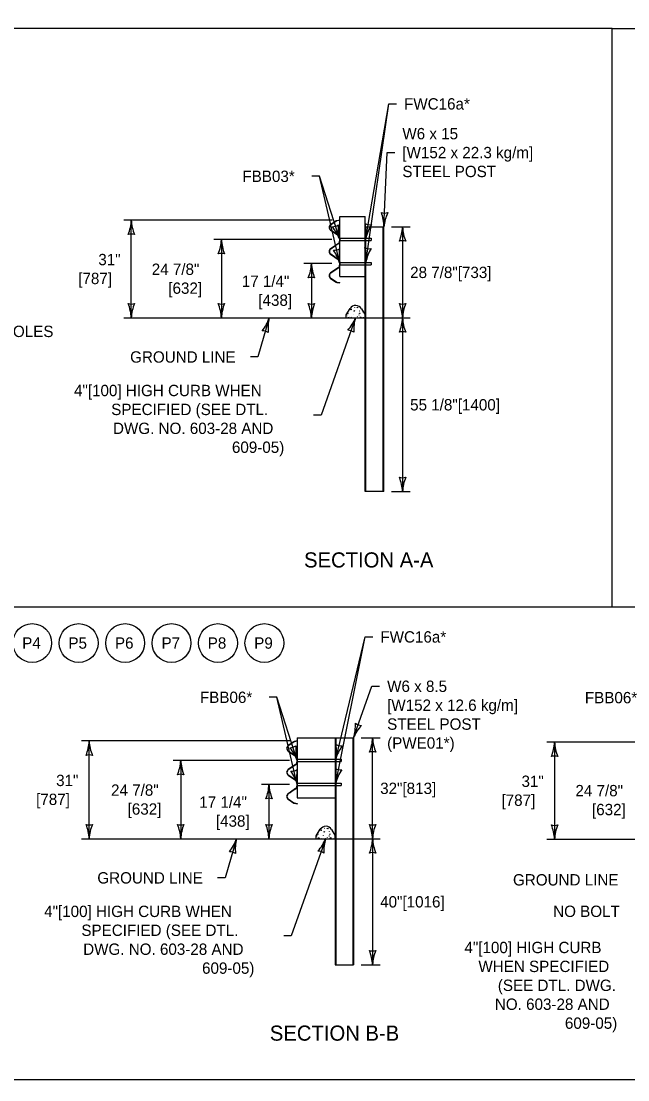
# Model space of a CAD drawing. Extents: x 49991 to 50160, y 49948 to 50051.
# Drawn here: x 50003.35 to 50006.56, y 49987.8 to 49993.4 of the extents above; entities that cross this region are included whole.
import ezdxf

# ---------------------------------------------------------------- set-up
doc = ezdxf.new("R2010")
doc.units = 0
for name, color, linetype in [('Level 1', 7, 'Continuous'), ('Level 2', 7, 'Continuous'), ('Level 3', 7, 'Continuous'), ('Level 4', 7, 'Continuous')]:
    doc.layers.add(name, color=color, linetype=linetype)

msp = doc.modelspace()

# ---------------------------------------------------------------- linework, layer by layer
at = {"layer": 'Level 1'}
for p, q in [((50005.0342, 49992.0461), (50005.0342, 49992.3628)), ((50005.0342, 49992.3628), (50005.1675, 49992.3628)), ((50005.1675, 49992.0461), (50005.1675, 49992.3628)), ((50004.9843, 49992.2945), (50004.9831, 49992.2932)), ((50005.0155, 49992.3402), (50004.9857, 49992.3201)), ((50005.0164, 49992.3388), (50004.9866, 49992.3186)), ((50005.0342, 49992.3443), (50005.0183, 49992.3414)), ((50005.0345, 49992.3426), (50005.0186, 49992.3397)), ((50005.0342, 49992.3443), (50005.032, 49992.3421)), ((50005.0345, 49992.3426), (50005.0342, 49992.3443)), ((50005.1675, 49990.9086), (50005.1675, 49992.3086)), ((50005.1675, 49992.3086), (50005.2675, 49992.3086)), ((50005.1718, 49990.9086), (50005.1718, 49992.3086)), ((50005.2632, 49990.9086), (50005.2632, 49992.3086)), ((50005.2675, 49990.9086), (50005.2675, 49992.3086)), ((50004.9857, 49992.2911), (50005.0255, 49992.2642)), ((50004.9866, 49992.2925), (50005.0265, 49992.2656)), ((50005.0193, 49992.2705), (50005.018, 49992.2692)), ((50005.0324, 49992.2511), (50005.0324, 49992.2328)), ((50005.0342, 49992.2511), (50005.0342, 49992.2328)), ((50005.1718, 49992.2482), (50005.2008, 49992.2482)), ((50005.2008, 49992.2482), (50005.2009, 49992.2357)), ((50005.0255, 49992.2197), (50004.9857, 49992.1928)), ((50005.0265, 49992.2183), (50004.9866, 49992.1913)), ((50005.1718, 49992.2357), (50005.2009, 49992.2357)), ((50004.9857, 49992.1638), (50005.0255, 49992.1369)), ((50004.9866, 49992.1652), (50005.0265, 49992.1383)), ((50005.0136, 49992.147), (50005.0124, 49992.1457)), ((50005.0255, 49992.0924), (50004.9857, 49992.0655)), ((50005.0265, 49992.091), (50004.9866, 49992.064)), ((50005.0023, 49992.0768), (50004.9958, 49992.0702)), ((50005.0324, 49992.1238), (50005.0324, 49992.1055)), ((50005.0342, 49992.1086), (50005.0324, 49992.1068)), ((50005.0342, 49992.1238), (50005.0342, 49992.1055)), ((50005.1718, 49992.1211), (50005.2008, 49992.1211)), ((50005.1718, 49992.1086), (50005.2009, 49992.1086)), ((50005.2008, 49992.1211), (50005.2009, 49992.1086)), ((50004.9801, 49992.0545), (50004.978, 49992.0524)), ((50004.9857, 49992.0365), (50005.0155, 49992.0164)), ((50004.9866, 49992.0379), (50005.0164, 49992.0178)), ((50005.0183, 49992.0152), (50005.0342, 49992.0123)), ((50005.0186, 49992.0169), (50005.0345, 49992.014)), ((50005.0342, 49992.0461), (50005.1675, 49992.0461)), ((50005.0342, 49992.0123), (50005.0345, 49992.014)), ((50005.0675, 49991.8434), (50005.0889, 49991.8773)), ((50005.1118, 49991.8838), (50005.1123, 49991.883)), ((50005.1374, 49991.8639), (50005.1379, 49991.8651)), ((50005.1376, 49991.8499), (50005.1388, 49991.8524)), ((50005.1487, 49991.8756), (50005.1675, 49991.8434)), ((50005.1577, 49991.8584), (50005.1581, 49991.8595)), ((50005.0675, 49991.8294), (50005.0675, 49991.8434)), ((50005.0675, 49991.8294), (50005.1675, 49991.8274)), ((50005.0707, 49991.843), (50005.0712, 49991.8422)), ((50005.0712, 49991.8427), (50005.0717, 49991.8419)), ((50005.0951, 49991.83), (50005.0956, 49991.8312)), ((50005.1059, 49991.843), (50005.1064, 49991.8442)), ((50005.1175, 49991.8284), (50005.1175, 49991.8284)), ((50005.1175, 49991.8284), (50005.1175, 49991.8284)), ((50005.1267, 49991.8331), (50005.1272, 49991.8343)), ((50005.1346, 49991.843), (50005.1351, 49991.8422)), ((50005.1351, 49991.8427), (50005.1356, 49991.8419)), ((50005.159, 49991.83), (50005.1595, 49991.8312)), ((50005.1675, 49991.8274), (50005.1675, 49991.8434)), ((50005.2675, 49990.9086), (50005.1675, 49990.9086)), ((49999.3835, 49990.2991), (50008.2653, 49990.2991)), ((50004.7911, 49989.5862), (50004.7613, 49989.5661)), ((50004.7921, 49989.5848), (50004.7623, 49989.5647)), ((50004.8099, 49989.5903), (50004.794, 49989.5874)), ((50004.8102, 49989.5886), (50004.7943, 49989.5857)), ((50004.8099, 49989.5903), (50004.8077, 49989.5881)), ((50004.8099, 49989.6067), (50004.8099, 49989.29)), ((50004.8099, 49989.6067), (50005.0099, 49989.6067)), ((50004.8102, 49989.5886), (50004.8099, 49989.5903)), ((50005.0099, 49989.6067), (50005.0099, 49989.29)), ((50005.0099, 49989.6067), (50005.0099, 49988.4067)), ((50005.0099, 49989.6067), (50005.107, 49989.6067)), ((50005.0131, 49989.6067), (50005.0131, 49988.4067)), ((50005.1038, 49989.6067), (50005.1038, 49988.4067)), ((50005.107, 49989.6067), (50005.107, 49988.4067)), ((50004.76, 49989.5405), (50004.7588, 49989.5392)), ((50004.7613, 49989.5371), (50004.8012, 49989.5102)), ((50004.7623, 49989.5386), (50004.8022, 49989.5117)), ((50004.795, 49989.5165), (50004.7937, 49989.5152)), ((50004.8081, 49989.4972), (50004.8081, 49989.4788)), ((50004.8099, 49989.4972), (50004.8099, 49989.4788)), ((50004.8012, 49989.4657), (50004.7613, 49989.4388)), ((50004.8022, 49989.4643), (50004.7623, 49989.4374)), ((50005.0131, 49989.4942), (50005.0421, 49989.4942)), ((50005.0131, 49989.4817), (50005.0421, 49989.4817)), ((50005.0421, 49989.4942), (50005.0421, 49989.4817)), ((50004.7613, 49989.4098), (50004.8012, 49989.3829)), ((50004.7623, 49989.4113), (50004.8022, 49989.3844)), ((50004.7893, 49989.393), (50004.7881, 49989.3918)), ((50004.8012, 49989.3384), (50004.7613, 49989.3115)), ((50004.8022, 49989.337), (50004.7623, 49989.3101)), ((50004.8081, 49989.3699), (50004.8081, 49989.3515)), ((50004.8099, 49989.3546), (50004.8081, 49989.3529)), ((50004.8099, 49989.3699), (50004.8099, 49989.3515)), ((50005.0131, 49989.3671), (50005.0421, 49989.3671)), ((50005.0131, 49989.3546), (50005.0421, 49989.3546)), ((50005.0421, 49989.3671), (50005.0421, 49989.3546)), ((50004.7558, 49989.3006), (50004.7537, 49989.2985)), ((50004.7613, 49989.2825), (50004.7911, 49989.2624)), ((50004.7623, 49989.284), (50004.7921, 49989.2638)), ((50004.778, 49989.3228), (50004.7715, 49989.3163)), ((50004.8099, 49989.29), (50005.0099, 49989.29)), ((50004.794, 49989.2612), (50004.8099, 49989.2583)), ((50004.7943, 49989.263), (50004.8102, 49989.26)), ((50004.8099, 49989.2583), (50004.8102, 49989.26)), ((50004.9099, 49989.0894), (50004.9312, 49989.1233)), ((50004.9541, 49989.1298), (50004.9546, 49989.129)), ((50004.9797, 49989.1099), (50004.9802, 49989.1111)), ((50004.991, 49989.1217), (50005.0099, 49989.0894)), ((50005, 49989.1045), (50005.0005, 49989.1055)), ((50004.9099, 49989.0754), (50004.9099, 49989.0894)), ((50004.9099, 49989.0754), (50005.0099, 49989.0734)), ((50004.913, 49989.089), (50004.9135, 49989.0882)), ((50004.9135, 49989.0887), (50004.9141, 49989.0879)), ((50004.9374, 49989.076), (50004.938, 49989.0772)), ((50004.9482, 49989.089), (50004.9488, 49989.0902)), ((50004.9599, 49989.0744), (50004.9599, 49989.0744)), ((50004.9599, 49989.0744), (50004.9599, 49989.0744)), ((50004.969, 49989.0791), (50004.9696, 49989.0803)), ((50004.9769, 49989.089), (50004.9774, 49989.0882)), ((50004.9774, 49989.0887), (50004.978, 49989.0879)), ((50004.98, 49989.0959), (50004.9812, 49989.0984)), ((50005.0013, 49989.076), (50005.0019, 49989.0772)), ((50005.0099, 49989.0734), (50005.0099, 49989.0894)), ((50005.0099, 49988.4067), (50005.107, 49988.4067))]:
    msp.add_line(p, q, dxfattribs=at)
msp.add_lwpolyline([(49999.3835, 49998.9992), (50016.7501, 49998.9992), (50016.7501, 49987.7988), (49999.3835, 49987.7988)], close=True, dxfattribs=at)
for points in [[(50006.474, 49990.2991), (50006.474, 49993.358), (49999.3835, 49993.358)], [(50006.474, 49993.358), (50011.2031, 49993.358), (50011.2031, 49987.7988)], [(50005.0737, 49991.8499), (50005.0753, 49991.8532), (50005.078, 49991.8512), (50005.0737, 49991.8499)], [(50005.0911, 49991.8708), (50005.0927, 49991.8741), (50005.0954, 49991.8721), (50005.0911, 49991.8708)], [(50005.1091, 49991.8626), (50005.1097, 49991.8665), (50005.1134, 49991.8626)], [(50005.1258, 49991.8803), (50005.1274, 49991.8837), (50005.13, 49991.8817), (50005.1258, 49991.8803)], [(50005.1403, 49991.8524), (50005.1419, 49991.8512), (50005.1376, 49991.8499)], [(50005.0785, 49991.8291), (50005.0807, 49991.8332), (50005.0825, 49991.8291)], [(50005.1417, 49991.8279), (50005.1446, 49991.8332), (50005.147, 49991.8278)], [(50004.9334, 49989.1168), (50004.935, 49989.1201), (50004.9377, 49989.1181), (50004.9334, 49989.1168)], [(50004.9515, 49989.1087), (50004.952, 49989.1125), (50004.9557, 49989.1087)], [(50004.9681, 49989.1263), (50004.9697, 49989.1297), (50004.9724, 49989.1277), (50004.9681, 49989.1263)], [(50004.9161, 49989.0959), (50004.9177, 49989.0993), (50004.9203, 49989.0973), (50004.9161, 49989.0959)], [(50004.9209, 49989.0752), (50004.923, 49989.0792), (50004.9249, 49989.0751)], [(50004.9827, 49989.0984), (50004.9842, 49989.0973), (50004.98, 49989.0959)], [(50004.9841, 49989.0739), (50004.9869, 49989.0792), (50004.9894, 49989.0738)]]:
    msp.add_lwpolyline(points, dxfattribs=at)
for centre, radius, start, end in [((50004.9955, 49992.3056), 0.0175, 124.048, 235.952), ((50004.9955, 49992.3056), 0.0157, 124.048, 235.952), ((50005.0196, 49992.3341), 0.00744, 100.4285, 124.048), ((50005.0196, 49992.3341), 0.00569, 100.4285, 124.048), ((50005.0167, 49992.2511), 0.0157, 0, 55.952), ((50005.0167, 49992.2511), 0.0175, 0, 55.952), ((50004.9955, 49992.1783), 0.0175, 124.048, 235.952), ((50004.9955, 49992.1783), 0.0157, 124.048, 235.952), ((50005.0167, 49992.2328), 0.0157, 304.048, 0), ((50005.0167, 49992.2328), 0.0175, 304.048, 0), ((50005.0167, 49992.1238), 0.0157, 0, 55.952), ((50005.0167, 49992.1238), 0.0175, 0, 55.952), ((50005.0167, 49992.1055), 0.0157, 304.048, 0), ((50005.0167, 49992.1055), 0.0175, 304.048, 0), ((50004.9955, 49992.051), 0.0175, 124.048, 235.952), ((50004.9955, 49992.051), 0.0157, 124.048, 235.952), ((50005.0196, 49992.0225), 0.00744, 235.952, 259.5715), ((50005.0196, 49992.0225), 0.00569, 235.952, 259.5715), ((50005.1183, 49991.8579), 0.0352, 30.1855, 146.6195), ((50004.7711, 49989.5516), 0.0175, 124.048, 235.952), ((50004.7711, 49989.5516), 0.0157, 124.048, 235.952), ((50004.7953, 49989.5801), 0.00744, 100.4285, 124.048), ((50004.7953, 49989.5801), 0.00569, 100.4285, 124.048), ((50004.7924, 49989.4972), 0.0157, 0, 55.952), ((50004.7924, 49989.4972), 0.0175, 0, 55.952), ((50004.7924, 49989.4788), 0.0157, 304.048, 0), ((50004.7924, 49989.4788), 0.0175, 304.048, 0), ((50004.7711, 49989.4243), 0.0175, 124.048, 235.952), ((50004.7711, 49989.4243), 0.0157, 124.048, 235.952), ((50004.7924, 49989.3699), 0.0175, 0, 55.952), ((50004.7924, 49989.3699), 0.0157, 0, 55.952), ((50004.7924, 49989.3515), 0.0157, 304.048, 0), ((50004.7924, 49989.3515), 0.0175, 304.048, 0), ((50004.7711, 49989.297), 0.0175, 124.048, 235.952), ((50004.7711, 49989.297), 0.0157, 124.048, 235.952), ((50004.7953, 49989.2685), 0.00744, 235.952, 259.5715), ((50004.7953, 49989.2685), 0.00569, 235.952, 259.5715), ((50004.9606, 49989.104), 0.0352, 30.1855, 146.6195)]:
    msp.add_arc(centre, radius, start, end, dxfattribs=at)
at = {"layer": 'Level 2'}
for centre in [(50003.4096, 49990.1082), (50003.6549, 49990.1082), (50003.9002, 49990.1082), (50004.1455, 49990.1082), (50004.3908, 49990.1082), (50004.6361, 49990.1082)]:
    msp.add_circle(centre, 0.1026, dxfattribs=at)
at = {"layer": 'Level 3'}
for p, q in [((50005.1718, 49992.2482), (50005.2938, 49992.959)), ((50005.1718, 49992.1211), (50005.2938, 49992.959)), ((50005.2938, 49992.959), (50005.3338, 49992.959)), ((50005.2675, 49992.3086), (50005.2849, 49992.7016)), ((50005.2849, 49992.7016), (50005.3249, 49992.7016)), ((50004.9263, 49992.5759), (50004.8863, 49992.5759)), ((50005.0342, 49992.2419), (50004.9263, 49992.5759)), ((50005.0342, 49992.115), (50004.9263, 49992.5759)), ((50004.9942, 49992.3443), (50003.893, 49992.3443)), ((50003.933, 49991.8273), (50003.933, 49992.3443)), ((50005.3075, 49992.3086), (50005.4059, 49992.3086)), ((50005.3659, 49992.3086), (50005.3659, 49991.8274)), ((50004.9924, 49992.2419), (50004.3689, 49992.2419)), ((50004.4089, 49992.2419), (50004.4089, 49991.8273)), ((50004.9924, 49992.1146), (50004.8444, 49992.1146)), ((50004.8844, 49992.1146), (50004.8844, 49991.8273)), ((50003.893, 49991.8274), (50005.4059, 49991.8274)), ((50004.6615, 49991.8274), (50004.6018, 49991.6207)), ((50005.1175, 49991.8284), (50004.9357, 49991.3135)), ((50005.3659, 49991.8274), (50005.3659, 49990.9086)), ((50004.6018, 49991.6207), (50004.5618, 49991.6207)), ((50004.9357, 49991.3135), (50004.8957, 49991.3135)), ((50005.3075, 49990.9086), (50005.4059, 49990.9086)), ((50005.0131, 49989.4942), (50005.1688, 49990.1406)), ((50005.0131, 49989.3671), (50005.1688, 49990.1406)), ((50005.1688, 49990.1406), (50005.2088, 49990.1406)), ((50005.107, 49989.6067), (50005.2044, 49989.8797)), ((50005.2044, 49989.8797), (50005.2444, 49989.8797)), ((50004.702, 49989.8213), (50004.662, 49989.8213)), ((50004.8099, 49989.4874), (50004.702, 49989.8213)), ((50004.8099, 49989.3611), (50004.702, 49989.8213)), ((50004.7699, 49989.5903), (50003.6705, 49989.5903)), ((50003.7105, 49989.0734), (50003.7105, 49989.5903)), ((50005.147, 49989.6067), (50005.2476, 49989.6067)), ((50005.2076, 49989.0734), (50005.2076, 49989.6067)), ((50006.7634, 49989.5842), (50006.1288, 49989.5842)), ((50006.1688, 49989.5842), (50006.1688, 49989.0706)), ((50004.7681, 49989.488), (50004.154, 49989.488)), ((50004.194, 49989.488), (50004.194, 49989.0734)), ((50004.7681, 49989.3607), (50004.6201, 49989.3607)), ((50004.6601, 49989.3607), (50004.6601, 49989.0734)), ((50003.6705, 49989.0734), (50005.2476, 49989.0734)), ((50004.4884, 49989.0734), (50004.4287, 49988.8667)), ((50004.9599, 49989.0744), (50004.778, 49988.5595)), ((50005.2076, 49989.0734), (50005.2076, 49988.4067)), ((50006.1288, 49989.0706), (50007.2412, 49989.0706)), ((50004.4287, 49988.8667), (50004.3887, 49988.8667)), ((50004.778, 49988.5595), (50004.738, 49988.5595)), ((50005.147, 49988.4067), (50005.2476, 49988.4067))]:
    msp.add_line(p, q, dxfattribs=at)
for centre, radius, start, end in [((50005.2732, 49992.4367), 0.0548, 249.601, 285.3234), ((50005.0345, 49992.3074), 0.233, 0.2895, 19.5394), ((50005.489, 49992.2896), 0.2223, 154.9182, 175.1017), ((50003.7109, 49992.3535), 0.2223, 337.456, 357.6395), ((50004.1657, 49992.3558), 0.233, 182.8273, 202.0772), ((50004.9948, 49992.3639), 0.0548, 270.0345, 305.7569), ((50004.8163, 49992.1595), 0.233, 20.723, 39.9729), ((50005.2484, 49992.3015), 0.2223, 175.3517, 195.5352), ((50005.1935, 49992.3746), 0.0548, 242.4025, 278.1249), ((50004.9405, 49992.2762), 0.233, 353.091, 12.3408), ((50005.3892, 49992.2016), 0.2223, 147.7197, 167.9032), ((50005.1437, 49992.3178), 0.2223, 337.456, 357.6395), ((50005.5986, 49992.3201), 0.233, 182.8273, 202.0772), ((50003.933, 49992.2161), 0.0548, 72.1388, 107.8612), ((50004.1868, 49992.2511), 0.2223, 337.456, 357.6395), ((50004.6416, 49992.2534), 0.233, 182.8273, 202.0772), ((50005.005, 49992.2398), 0.0548, 265.3085, 301.0309), ((50004.8102, 49992.0508), 0.233, 15.997, 35.2468), ((50005.2526, 49992.1567), 0.2223, 170.6257, 190.8092), ((50005.1903, 49992.248), 0.0548, 243.857, 279.5794), ((50004.9399, 49992.1433), 0.233, 354.5455, 13.7954), ((50005.3903, 49992.08), 0.2223, 149.1742, 169.3577), ((50005.3659, 49992.1804), 0.0548, 72.1388, 107.8612), ((50004.4089, 49992.1137), 0.0548, 72.1388, 107.8612), ((50004.6623, 49992.1238), 0.2223, 337.456, 357.6395), ((50005.1171, 49992.1261), 0.233, 182.8273, 202.0772), ((50004.8844, 49991.9864), 0.0548, 72.1388, 107.8612), ((50003.933, 49991.9556), 0.0548, 252.1388, 287.8612), ((50003.7003, 49991.8159), 0.233, 2.8273, 22.0772), ((50004.1552, 49991.8182), 0.2223, 157.456, 177.6395), ((50004.4089, 49991.9556), 0.0548, 252.1388, 287.8612), ((50004.1762, 49991.8159), 0.233, 2.8273, 22.0772), ((50004.631, 49991.8182), 0.2223, 157.456, 177.6395), ((50004.8844, 49991.9556), 0.0548, 252.1388, 287.8612), ((50004.6517, 49991.8159), 0.233, 2.8273, 22.0772), ((50005.1066, 49991.8182), 0.2223, 157.456, 177.6395), ((50005.3659, 49991.9556), 0.0548, 252.1388, 287.8612), ((50005.1332, 49991.8159), 0.233, 2.8273, 22.0772), ((50005.588, 49991.8182), 0.2223, 157.456, 177.6395), ((50004.4507, 49991.8978), 0.2223, 321.3407, 341.5242), ((50004.8883, 49991.7738), 0.233, 166.712, 185.9619), ((50004.9111, 49991.911), 0.2223, 318.0037, 338.1872), ((50005.3408, 49991.7617), 0.233, 163.375, 182.6248), ((50005.1437, 49991.8365), 0.2223, 337.456, 357.6395), ((50005.5986, 49991.8388), 0.233, 182.8273, 202.0772), ((50004.626, 49991.7042), 0.0548, 56.0235, 91.7459), ((50005.0748, 49991.7075), 0.0548, 52.6865, 88.4089), ((50005.3659, 49991.6991), 0.0548, 72.1388, 107.8612), ((50005.3659, 49991.0368), 0.0548, 252.1388, 287.8612), ((50005.1332, 49990.8971), 0.233, 2.8273, 22.0772), ((50005.588, 49990.8994), 0.2223, 157.456, 177.6395), ((50004.884, 49989.6741), 0.233, 343.1881, 2.438), ((50005.3131, 49989.5234), 0.2223, 137.8168, 158.0003), ((50005.1501, 49989.7275), 0.0548, 232.4996, 268.222), ((50003.4884, 49989.5995), 0.2223, 337.456, 357.6395), ((50003.9432, 49989.6018), 0.233, 182.8273, 202.0772), ((50004.7705, 49989.6094), 0.0548, 270.0345, 305.7569), ((50004.5919, 49989.4049), 0.233, 20.723, 39.9729), ((50005.0241, 49989.5469), 0.2223, 175.3517, 195.5352), ((50004.7842, 49989.5376), 0.233, 349.2812, 8.531), ((50005.2269, 49989.4333), 0.2223, 143.9099, 164.0934), ((50005.0431, 49989.6189), 0.0548, 238.5927, 274.315), ((50004.9855, 49989.6159), 0.2223, 337.456, 357.6395), ((50005.4403, 49989.6182), 0.233, 182.8273, 202.0772), ((50005.9467, 49989.5933), 0.2223, 337.456, 357.6395), ((50006.4015, 49989.5957), 0.233, 182.8273, 202.0772), ((50003.7105, 49989.4621), 0.0548, 72.1388, 107.8612), ((50005.2076, 49989.4785), 0.0548, 72.1388, 107.8612), ((50006.1688, 49989.456), 0.0548, 72.1388, 107.8612), ((50003.9718, 49989.4971), 0.2223, 337.456, 357.6395), ((50004.4267, 49989.4995), 0.233, 182.8273, 202.0772), ((50005.0384, 49989.4928), 0.0548, 240.7547, 276.4771), ((50004.7827, 49989.4018), 0.233, 351.4432, 10.6931), ((50004.194, 49989.3597), 0.0548, 72.1388, 107.8612), ((50004.7806, 49989.4859), 0.0548, 265.3249, 301.0472), ((50004.5859, 49989.2968), 0.233, 16.0134, 35.2632), ((50005.0282, 49989.4028), 0.2223, 170.6421, 190.8256), ((50005.229, 49989.3143), 0.2223, 146.0719, 166.2554), ((50004.438, 49989.3698), 0.2223, 337.456, 357.6395), ((50004.8928, 49989.3722), 0.233, 182.8273, 202.0772), ((50004.6601, 49989.2325), 0.0548, 72.1388, 107.8612), ((50003.7105, 49989.2016), 0.0548, 252.1388, 287.8612), ((50003.4778, 49989.0619), 0.233, 2.8273, 22.0772), ((50003.9326, 49989.0642), 0.2223, 157.456, 177.6395), ((50004.194, 49989.2016), 0.0548, 252.1388, 287.8612), ((50003.9613, 49989.0619), 0.233, 2.8273, 22.0772), ((50004.4161, 49989.0642), 0.2223, 157.456, 177.6395), ((50004.6601, 49989.2016), 0.0548, 252.1388, 287.8612), ((50004.4274, 49989.0619), 0.233, 2.8273, 22.0772), ((50004.8822, 49989.0642), 0.2223, 157.456, 177.6395), ((50005.2076, 49989.2016), 0.0548, 252.1388, 287.8612), ((50004.9749, 49989.0619), 0.233, 2.8273, 22.0772), ((50005.4297, 49989.0642), 0.2223, 157.456, 177.6395), ((50006.1688, 49989.1988), 0.0548, 252.1388, 287.8612), ((50005.9361, 49989.0591), 0.233, 2.8273, 22.0772), ((50006.391, 49989.0614), 0.2223, 157.456, 177.6395), ((50004.2775, 49989.1438), 0.2223, 321.3407, 341.5242), ((50004.7152, 49989.0198), 0.233, 166.712, 185.9619), ((50004.7535, 49989.157), 0.2223, 318.0037, 338.1872), ((50005.1831, 49989.0077), 0.233, 163.375, 182.6248), ((50004.9855, 49989.0825), 0.2223, 337.456, 357.6395), ((50005.4403, 49989.0849), 0.233, 182.8273, 202.0772), ((50004.4528, 49988.9502), 0.0548, 56.0235, 91.7459), ((50004.9172, 49988.9535), 0.0548, 52.6865, 88.4089), ((50005.2076, 49988.9452), 0.0548, 72.1388, 107.8612), ((50005.2076, 49988.5349), 0.0548, 252.1388, 287.8612), ((50004.9749, 49988.3952), 0.233, 2.8273, 22.0772), ((50005.4297, 49988.3976), 0.2223, 157.456, 177.6395)]:
    msp.add_arc(centre, radius, start, end, dxfattribs=at)
at = {"layer": 'Level 4'}
for p, q in [((50005.0342, 49992.2482), (50005.1718, 49992.2482)), ((50005.0342, 49992.2357), (50005.1718, 49992.2357)), ((50005.0342, 49992.1211), (50005.1718, 49992.1211)), ((50005.0342, 49992.1086), (50005.1718, 49992.1086)), ((50004.8099, 49989.4942), (50005.0131, 49989.4942)), ((50004.8099, 49989.4817), (50005.0131, 49989.4817)), ((50004.8099, 49989.3671), (50005.0131, 49989.3671)), ((50004.8099, 49989.3546), (50005.0131, 49989.3546))]:
    msp.add_line(p, q, dxfattribs=at)

# ---------------------------------------------------------------- texts
at = {"layer": 'Level 2'}
for s, height, p in [('FWC16a*', 0.06, (50005.3738, 49992.929)), ('W6 x 15', 0.06, (50005.3649, 49992.7716)), ('[W152 x 22.3 kg/m]', 0.06, (50005.3649, 49992.6716)), ('STEEL POST', 0.06, (50005.3649, 49992.5716)), ('FBB03*', 0.06, (50004.5199, 49992.5459)), ('31"', 0.06, (50003.7585, 49992.1058)), ('24 7/8"', 0.06, (50004.0409, 49992.0546)), ('28 7/8"[733]', 0.06, (50005.4059, 49992.038)), ('[787]', 0.06, (50003.6526, 49992.0058)), ('[632]', 0.06, (50004.1285, 49991.9546)), ('17 1/4"', 0.06, (50004.5164, 49991.991)), ('[438]', 0.06, (50004.604, 49991.891)), ('DIA. HOLES', 0.06, (50003.0713, 49991.7261)), ('GROUND LINE', 0.06, (50003.9267, 49991.5907)), ('4"[100] HIGH CURB WHEN ', 0.06, (50003.6302, 49991.4135)), ('55 1/8"[1400]', 0.06, (50005.4059, 49991.338)), ('SPECIFIED (SEE DTL. ', 0.06, (50003.8269, 49991.3135)), ('DWG. NO. 603-28 AND ', 0.06, (50003.8363, 49991.2135)), ('609-05) ', 0.06, (50004.4645, 49991.1135)), ('SECTION A-A', 0.08, (50004.8455, 49990.5077)), ('FWC16a*', 0.06, (50005.2488, 49990.1106)), ('P4', 0.06, (50003.3565, 49990.0784)), ('P5', 0.06, (50003.6007, 49990.0783)), ('P6', 0.06, (50003.8466, 49990.0784)), ('P7', 0.06, (50004.0925, 49990.0784)), ('P8', 0.06, (50004.3366, 49990.0783)), ('P9', 0.06, (50004.5823, 49990.0783)), ('W6 x 8.5', 0.06, (50005.2844, 49989.8497)), ('FBB06*', 0.06, (50004.2955, 49989.7913)), ('FBB06*', 0.06, (50006.3291, 49989.7896)), ('[W152 x 12.6 kg/m]', 0.06, (50005.2844, 49989.7497)), ('STEEL POST', 0.06, (50005.2844, 49989.6497)), ('(PWE01*)', 0.06, (50005.2844, 49989.5497)), ('31"', 0.06, (50003.5359, 49989.3519)), ('31"', 0.06, (50005.9943, 49989.3474)), ('24 7/8"', 0.06, (50003.826, 49989.3007)), ('32"[813]', 0.06, (50005.2476, 49989.31)), ('24 7/8"', 0.06, (50006.279, 49989.2979)), ('[787]', 0.06, (50003.4301, 49989.2519)), ('17 1/4"', 0.06, (50004.2921, 49989.237)), ('[787]', 0.06, (50005.8884, 49989.2474)), ('[632]', 0.06, (50003.9135, 49989.2007)), ('[632]', 0.06, (50006.3666, 49989.1979)), ('[438]', 0.06, (50004.3797, 49989.137)), ('GROUND LINE', 0.06, (50003.7535, 49988.8367)), ('GROUND LINE', 0.06, (50005.9493, 49988.8263)), ('40"[1016]', 0.06, (50005.2476, 49988.71)), ('4"[100] HIGH CURB WHEN ', 0.06, (50003.4726, 49988.6595)), ('NO BOLT', 0.06, (50006.1615, 49988.6598)), ('SPECIFIED (SEE DTL. ', 0.06, (50003.6692, 49988.5595)), ('DWG. NO. 603-28 AND ', 0.06, (50003.6787, 49988.4595)), ('4"[100] HIGH CURB', 0.06, (50005.6928, 49988.4686)), ('609-05) ', 0.06, (50004.3068, 49988.3595)), ('WHEN SPECIFIED ', 0.06, (50005.7667, 49988.3686)), ('(SEE DTL. DWG. ', 0.06, (50005.8691, 49988.2686)), ('NO. 603-28 AND ', 0.06, (50005.8536, 49988.1686)), ('609-05) ', 0.06, (50006.2236, 49988.0686)), ('SECTION B-B', 0.08, (50004.6647, 49988.0058))]:
    msp.add_text(s, height=height, dxfattribs=at).set_placement(p)

doc.saveas('drawing.dxf')
